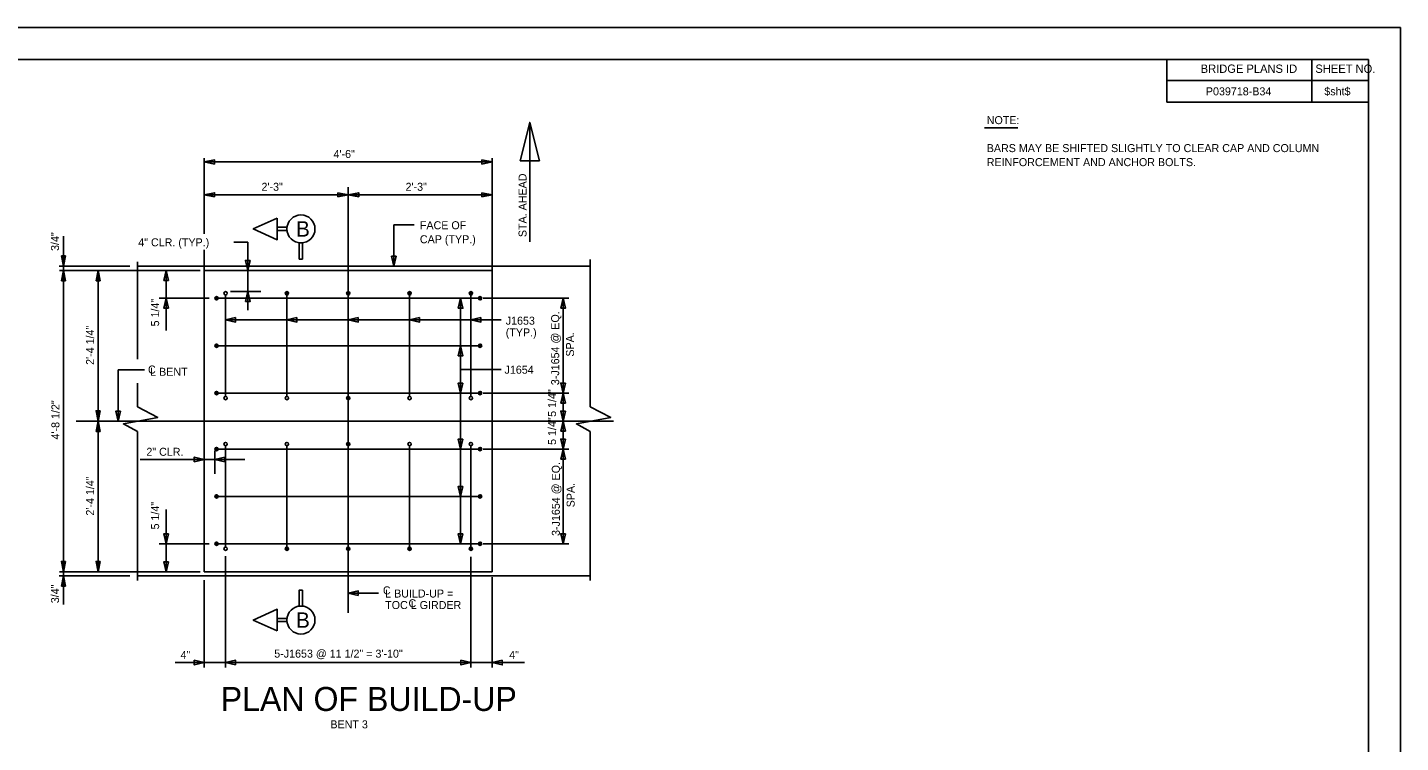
# Model space of a CAD drawing. Extents: x 1970675.2 to 1970711.3, y 796145.2 to 796167.2.
# Drawn here: x 1970689.79 to 1970711.24, y 796156.08 to 796167.25 of the extents above; entities that cross this region are included whole.
import ezdxf

# ---------------------------------------------------------------- set-up
doc = ezdxf.new("R2010")
doc.units = 0
for name, color, linetype in [('BR_AUTO DIMENSION', 7, 'Continuous'), ('BR_BORDER LINES', 7, 'Continuous'), ('BR_CENTER LINES', 7, 'Continuous'), ('BR_CONCRETE', 7, 'Continuous'), ('BR_REBAR', 7, 'Continuous'), ('BR_TEXT', 7, 'Continuous'), ('Default', 7, 'Continuous'), ('Level 31', 7, 'Continuous')]:
    doc.layers.add(name, color=color, linetype=linetype)

msp = doc.modelspace()

# ---------------------------------------------------------------- linework, layer by layer
at = {"layer": 'BR_AUTO DIMENSION'}
for p, q in [((1970697.636, 796165.764), (1970697.636, 796163.9)), ((1970704.74, 796165.678), (1970705.258, 796165.678)), ((1970692.55, 796164.025), (1970692.55, 796165.207)), ((1970697.05, 796163.452), (1970697.05, 796165.207)), ((1970692.55, 796165.145), (1970697.05, 796165.145)), ((1970694.8, 796164.751), (1970694.8, 796164.386)), ((1970692.55, 796164.632), (1970694.8, 796164.632)), ((1970697.05, 796164.632), (1970694.8, 796164.632)), ((1970695.514, 796164.165), (1970695.514, 796163.515)), ((1970695.514, 796164.165), (1970695.831, 796164.165)), ((1970690.351, 796163.452), (1970690.351, 796163.985)), ((1970693.23, 796163.89), (1970693.013, 796163.89)), ((1970693.23, 796162.831), (1970693.23, 796163.89)), ((1970692.55, 796163.452), (1970692.55, 796163.771)), ((1970691.386, 796163.515), (1970690.285, 796163.515)), ((1970692.488, 796163.452), (1970690.289, 796163.452)), ((1970690.351, 796158.744), (1970690.351, 796163.452)), ((1970690.893, 796163.452), (1970690.893, 796161.098)), ((1970691.956, 796163.452), (1970691.956, 796162.513)), ((1970692.962, 796163.119), (1970693.437, 796163.119)), ((1970692.629, 796163.015), (1970691.849, 796163.015)), ((1970696.554, 796163.015), (1970696.554, 796159.181)), ((1970696.905, 796163.015), (1970698.248, 796163.015)), ((1970698.156, 796161.535), (1970698.156, 796163.015)), ((1970692.884, 796162.681), (1970697.189, 796162.681)), ((1970691.207, 796161.897), (1970691.207, 796161.098)), ((1970691.619, 796161.897), (1970691.207, 796161.897)), ((1970696.554, 796161.902), (1970697.189, 796161.902)), ((1970696.905, 796161.535), (1970698.248, 796161.535)), ((1970698.156, 796161.535), (1970698.156, 796160.66)), ((1970690.836, 796161.098), (1970690.972, 796161.098)), ((1970690.893, 796161.098), (1970690.893, 796158.744)), ((1970696.905, 796160.66), (1970698.248, 796160.66)), ((1970698.156, 796159.181), (1970698.156, 796160.66)), ((1970693.186, 796160.498), (1970691.551, 796160.498)), ((1970692.717, 796160.63), (1970692.717, 796160.275)), ((1970691.956, 796158.744), (1970691.956, 796159.718)), ((1970692.629, 796159.181), (1970691.849, 796159.181)), ((1970696.905, 796159.181), (1970698.248, 796159.181)), ((1970692.884, 796158.988), (1970692.884, 796157.249)), ((1970696.717, 796158.975), (1970696.717, 796157.249)), ((1970692.488, 796158.744), (1970690.289, 796158.744)), ((1970690.351, 796158.744), (1970690.351, 796158.233)), ((1970691.386, 796158.681), (1970690.285, 796158.681)), ((1970692.55, 796158.61), (1970692.55, 796157.249)), ((1970697.05, 796158.661), (1970697.05, 796157.249)), ((1970694.8, 796158.408), (1970695.272, 796158.408)), ((1970692.094, 796157.324), (1970697.552, 796157.324))]:
    msp.add_line(p, q, dxfattribs=at)
for points in [[(1970692.713, 796165.113), (1970692.55, 796165.145), (1970692.713, 796165.176)], [(1970696.888, 796165.176), (1970697.05, 796165.145), (1970696.888, 796165.113)], [(1970692.713, 796164.601), (1970692.55, 796164.632), (1970692.713, 796164.664)], [(1970694.638, 796164.664), (1970694.8, 796164.632), (1970694.638, 796164.601)], [(1970694.963, 796164.601), (1970694.8, 796164.632), (1970694.963, 796164.664)], [(1970696.888, 796164.664), (1970697.05, 796164.632), (1970696.888, 796164.601)], [(1970690.32, 796163.677), (1970690.351, 796163.515), (1970690.382, 796163.677)], [(1970695.55, 796163.671), (1970695.514, 796163.515), (1970695.478, 796163.671)], [(1970690.32, 796163.29), (1970690.351, 796163.452), (1970690.382, 796163.29)], [(1970690.862, 796163.29), (1970690.893, 796163.452), (1970690.924, 796163.29)], [(1970691.992, 796163.296), (1970691.956, 796163.452), (1970691.92, 796163.296)], [(1970693.266, 796163.608), (1970693.23, 796163.452), (1970693.194, 796163.608)], [(1970693.194, 796162.963), (1970693.23, 796163.119), (1970693.266, 796162.963)], [(1970691.992, 796162.859), (1970691.956, 796163.015), (1970691.92, 796162.859)], [(1970696.518, 796162.859), (1970696.554, 796163.015), (1970696.59, 796162.859)], [(1970698.12, 796162.859), (1970698.156, 796163.015), (1970698.192, 796162.859)], [(1970693.04, 796162.717), (1970692.884, 796162.681), (1970693.04, 796162.645)], [(1970693.998, 796162.717), (1970693.842, 796162.681), (1970693.998, 796162.645)], [(1970694.956, 796162.717), (1970694.8, 796162.681), (1970694.956, 796162.645)], [(1970695.915, 796162.717), (1970695.759, 796162.681), (1970695.915, 796162.645)], [(1970696.873, 796162.717), (1970696.717, 796162.681), (1970696.873, 796162.645)], [(1970696.518, 796162.119), (1970696.554, 796162.275), (1970696.59, 796162.119)], [(1970696.59, 796161.691), (1970696.554, 796161.535), (1970696.518, 796161.691)], [(1970698.192, 796161.691), (1970698.156, 796161.535), (1970698.12, 796161.691)], [(1970698.12, 796161.379), (1970698.156, 796161.535), (1970698.192, 796161.379)], [(1970690.924, 796161.26), (1970690.893, 796161.098), (1970690.862, 796161.26)], [(1970690.862, 796160.935), (1970690.893, 796161.098), (1970690.924, 796160.935)], [(1970691.243, 796161.254), (1970691.207, 796161.098), (1970691.171, 796161.254)], [(1970698.192, 796161.254), (1970698.156, 796161.098), (1970698.12, 796161.254)], [(1970698.12, 796160.942), (1970698.156, 796161.098), (1970698.192, 796160.942)], [(1970696.59, 796160.816), (1970696.554, 796160.66), (1970696.518, 796160.816)], [(1970698.192, 796160.816), (1970698.156, 796160.66), (1970698.12, 796160.816)], [(1970698.12, 796160.504), (1970698.156, 796160.66), (1970698.192, 796160.504)], [(1970692.394, 796160.462), (1970692.55, 796160.498), (1970692.394, 796160.534)], [(1970692.873, 796160.534), (1970692.717, 796160.498), (1970692.873, 796160.462)], [(1970696.59, 796160.077), (1970696.554, 796159.921), (1970696.518, 796160.077)], [(1970691.992, 796159.337), (1970691.956, 796159.181), (1970691.92, 796159.337)], [(1970696.59, 796159.337), (1970696.554, 796159.181), (1970696.518, 796159.337)], [(1970698.192, 796159.337), (1970698.156, 796159.181), (1970698.12, 796159.337)], [(1970690.382, 796158.906), (1970690.351, 796158.744), (1970690.32, 796158.906)], [(1970690.924, 796158.906), (1970690.893, 796158.744), (1970690.862, 796158.906)], [(1970691.992, 796158.9), (1970691.956, 796158.744), (1970691.92, 796158.9)], [(1970690.32, 796158.519), (1970690.351, 796158.681), (1970690.382, 796158.519)], [(1970694.956, 796158.372), (1970694.8, 796158.408), (1970694.956, 796158.444)], [(1970692.394, 796157.36), (1970692.55, 796157.324), (1970692.394, 796157.288)], [(1970693.04, 796157.288), (1970692.884, 796157.324), (1970693.04, 796157.36)], [(1970696.561, 796157.36), (1970696.717, 796157.324), (1970696.561, 796157.288)], [(1970697.206, 796157.36), (1970697.05, 796157.324), (1970697.206, 796157.288)]]:
    msp.add_lwpolyline(points, close=True, dxfattribs=at)
at = {"layer": 'BR_BORDER LINES'}
for p, q in [((1970710.736, 796166.746), (1970677.07, 796166.746)), ((1970707.584, 796166.08), (1970707.584, 796166.746)), ((1970709.85, 796166.08), (1970709.85, 796166.746)), ((1970710.736, 796145.746), (1970710.736, 796166.746)), ((1970707.584, 796166.417), (1970710.736, 796166.417)), ((1970709.85, 796166.417), (1970710.736, 796166.417)), ((1970710.736, 796166.08), (1970707.584, 796166.08))]:
    msp.add_line(p, q, dxfattribs=at)
at = {"layer": 'BR_CENTER LINES'}
for p, q in [((1970694.8, 796164.632), (1970694.8, 796158.104)), ((1970690.551, 796161.098), (1970698.943, 796161.098))]:
    msp.add_line(p, q, dxfattribs=at)
at = {"layer": 'BR_CONCRETE'}
for p, q in [((1970691.506, 796163.515), (1970698.58, 796163.515)), ((1970692.55, 796163.452), (1970697.05, 796163.452)), ((1970692.55, 796163.452), (1970692.55, 796161.098)), ((1970697.05, 796163.452), (1970697.05, 796161.098)), ((1970692.55, 796161.098), (1970692.55, 796158.744)), ((1970692.55, 796161.098), (1970697.05, 796161.098)), ((1970697.05, 796161.098), (1970697.05, 796158.744)), ((1970692.55, 796158.744), (1970697.05, 796158.744)), ((1970691.506, 796158.681), (1970698.58, 796158.681))]:
    msp.add_line(p, q, dxfattribs=at)
at = {"layer": 'BR_REBAR'}
for p, q in [((1970692.884, 796161.483), (1970692.884, 796163.067)), ((1970693.842, 796161.483), (1970693.842, 796163.119)), ((1970694.8, 796161.483), (1970694.8, 796163.119)), ((1970695.759, 796161.483), (1970695.759, 796163.119)), ((1970696.717, 796161.483), (1970696.717, 796163.119)), ((1970692.717, 796163.015), (1970696.884, 796163.015)), ((1970692.717, 796162.275), (1970696.884, 796162.275)), ((1970692.717, 796161.535), (1970696.884, 796161.535)), ((1970692.717, 796160.66), (1970696.884, 796160.66)), ((1970692.884, 796159.129), (1970692.884, 796160.713)), ((1970693.842, 796159.077), (1970693.842, 796160.712)), ((1970694.8, 796159.077), (1970694.8, 796160.712)), ((1970695.759, 796159.077), (1970695.759, 796160.712)), ((1970696.717, 796159.077), (1970696.717, 796160.712)), ((1970692.717, 796159.921), (1970696.884, 796159.921)), ((1970692.717, 796159.181), (1970696.884, 796159.181))]:
    msp.add_line(p, q, dxfattribs=at)
for centre, radius in [((1970692.743, 796163.015), 0.026), ((1970692.884, 796163.093), 0.0261), ((1970693.842, 796163.093), 0.0261), ((1970694.8, 796163.093), 0.0261), ((1970695.759, 796163.093), 0.0261), ((1970696.717, 796163.093), 0.0261), ((1970696.858, 796163.015), 0.026), ((1970692.743, 796162.275), 0.026), ((1970696.858, 796162.275), 0.026), ((1970692.743, 796161.535), 0.026), ((1970696.858, 796161.535), 0.026), ((1970692.884, 796161.457), 0.0261), ((1970693.842, 796161.457), 0.0261), ((1970694.8, 796161.457), 0.0261), ((1970695.759, 796161.457), 0.0261), ((1970696.717, 796161.457), 0.0261), ((1970692.743, 796160.66), 0.026), ((1970692.884, 796160.739), 0.0261), ((1970693.842, 796160.739), 0.0261), ((1970694.8, 796160.739), 0.0261), ((1970695.759, 796160.739), 0.0261), ((1970696.717, 796160.739), 0.0261), ((1970696.858, 796160.66), 0.026), ((1970692.743, 796159.921), 0.026), ((1970696.858, 796159.921), 0.026), ((1970692.743, 796159.181), 0.026), ((1970696.858, 796159.181), 0.026), ((1970692.884, 796159.103), 0.0261), ((1970693.842, 796159.103), 0.0261), ((1970694.8, 796159.103), 0.0261), ((1970695.759, 796159.103), 0.0261), ((1970696.717, 796159.103), 0.0261)]:
    msp.add_circle(centre, radius, dxfattribs=at)
at = {"layer": 'BR_TEXT'}
for points in [[(1970693.692, 796164.267), (1970693.317, 796164.099), (1970693.692, 796163.93)], [(1970693.842, 796164.074), (1970693.692, 796164.074), (1970693.692, 796164.124), (1970693.842, 796164.124)], [(1970694.086, 796163.629), (1970694.036, 796163.629), (1970694.036, 796163.88), (1970694.086, 796163.88)], [(1970694.086, 796158.458), (1970694.036, 796158.458), (1970694.036, 796158.208), (1970694.086, 796158.208)], [(1970693.692, 796157.82), (1970693.317, 796157.989), (1970693.692, 796158.158)], [(1970693.842, 796158.014), (1970693.692, 796158.014), (1970693.692, 796157.964), (1970693.842, 796157.964)]]:
    msp.add_lwpolyline(points, close=True, dxfattribs=at)
for centre in [(1970694.061, 796164.099), (1970694.061, 796157.989)]:
    msp.add_circle(centre, 0.219, dxfattribs=at)
at = {"layer": 'Default'}
for p, q in [((1970691.506, 796163.583), (1970691.506, 796162.063)), ((1970698.58, 796163.622), (1970698.58, 796161.319)), ((1970691.506, 796161.692), (1970691.506, 796161.319)), ((1970691.506, 796160.936), (1970691.506, 796158.609)), ((1970698.58, 796160.936), (1970698.58, 796158.609))]:
    msp.add_line(p, q, dxfattribs=at)
msp.add_lwpolyline([(1970697.786, 796165.164), (1970697.636, 796165.764), (1970697.486, 796165.164)], close=True, dxfattribs=at)
for points in [[(1970691.506, 796160.936), (1970691.289, 796161.054), (1970691.825, 796161.154), (1970691.506, 796161.319)], [(1970698.58, 796160.936), (1970698.364, 796161.054), (1970698.9, 796161.154), (1970698.58, 796161.319)]]:
    msp.add_lwpolyline(points, dxfattribs=at)
at = {"layer": 'Level 31'}
msp.add_line((1970711.236, 796167.246), (1970675.236, 796167.246), dxfattribs=at)
msp.add_lwpolyline([(1970675.236, 796167.246), (1970675.236, 796145.246), (1970711.236, 796145.246), (1970711.236, 796167.246)], dxfattribs=at)

# ---------------------------------------------------------------- texts
at = {"layer": 'BR_AUTO DIMENSION'}
for s, p in [('NOTE:', (1970704.773, 796165.736)), ('BARS MAY BE SHIFTED SLIGHTLY TO CLEAR CAP AND COLUMN', (1970704.773, 796165.299)), ('4\'-6"', (1970694.57, 796165.207)), ('REINFORCEMENT AND ANCHOR BOLTS.', (1970704.773, 796165.08)), ('2\'-3"', (1970693.445, 796164.695)), ('2\'-3"', (1970695.695, 796164.695)), ('FACE OF', (1970695.919, 796164.094)), ('4" CLR. (TYP.)', (1970691.52, 796163.827)), ('CAP (TYP.)', (1970695.919, 796163.875)), ('J1653', (1970697.26, 796162.603)), ('(TYP.)', (1970697.26, 796162.42)), ('J1654', (1970697.241, 796161.837)), ('2" CLR.', (1970691.647, 796160.555)), ('C', (1970695.342, 796158.39)), ('L BUILD-UP = ', (1970695.377, 796158.341)), ('C', (1970695.741, 796158.189)), ('TOC L GIRDER', (1970695.377, 796158.161)), ('5-J1653 @ 11 1/2" = 3\'-10"', (1970693.644, 796157.402)), ('BENT 3', (1970694.521, 796156.297))]:
    msp.add_text(s, height=0.125, dxfattribs=at).set_placement(p)
for s, rotation, p in [('STA. AHEAD', 90, (1970697.585, 796163.971)), ('3-J1654 @ EQ. ', 90, (1970698.095, 796161.658)), ('2\'-4 1/4"', 90, (1970690.83, 796161.975)), ('SPA. ', 90, (1970698.326, 796162.104)), ('4\'-8 1/2"', 90, (1970690.289, 796160.81)), ('3-J1654 @ EQ. ', 90, (1970698.105, 796159.303)), ('2\'-4 1/4"', 90, (1970690.83, 796159.621)), ('SPA. ', 90, (1970698.336, 796159.75)), ('4"', 360, (1970692.18, 796157.382)), ('4"', 360, (1970697.314, 796157.382))]:
    msp.add_text(s, height=0.125, rotation=rotation, dxfattribs=at).set_placement(p)
at = {"layer": 'BR_TEXT'}
for s, height, p in [('BRIDGE PLANS ID', 0.13, (1970708.115, 796166.537)), ('SHEET NO.', 0.13, (1970709.906, 796166.537)), ('P039718-B34', 0.125, (1970708.196, 796166.186)), ('$sht$', 0.125, (1970710.046, 796166.186)), ('B', 0.24, (1970693.986, 796163.979)), ('B', 0.24, (1970693.986, 796157.869)), ('PLAN OF BUILD-UP', 0.375, (1970692.808, 796156.569))]:
    msp.add_text(s, height=height, dxfattribs=at).set_placement(p)
for s, rotation, p in [('3/4"', 90, (1970690.282, 796163.755)), ('5 1/4"', 90, (1970691.846, 796162.576)), ('C', 360, (1970691.672, 796161.84)), ('L BENT', 360, (1970691.706, 796161.805)), ('5 1/4"', 90, (1970698.046, 796161.163)), ('5 1/4"', 90, (1970698.046, 796160.725)), ('5 1/4"', 90, (1970691.846, 796159.404)), ('3/4"', 90, (1970690.282, 796158.252))]:
    msp.add_text(s, height=0.125, rotation=rotation, dxfattribs=at).set_placement(p)

doc.saveas('drawing.dxf')
